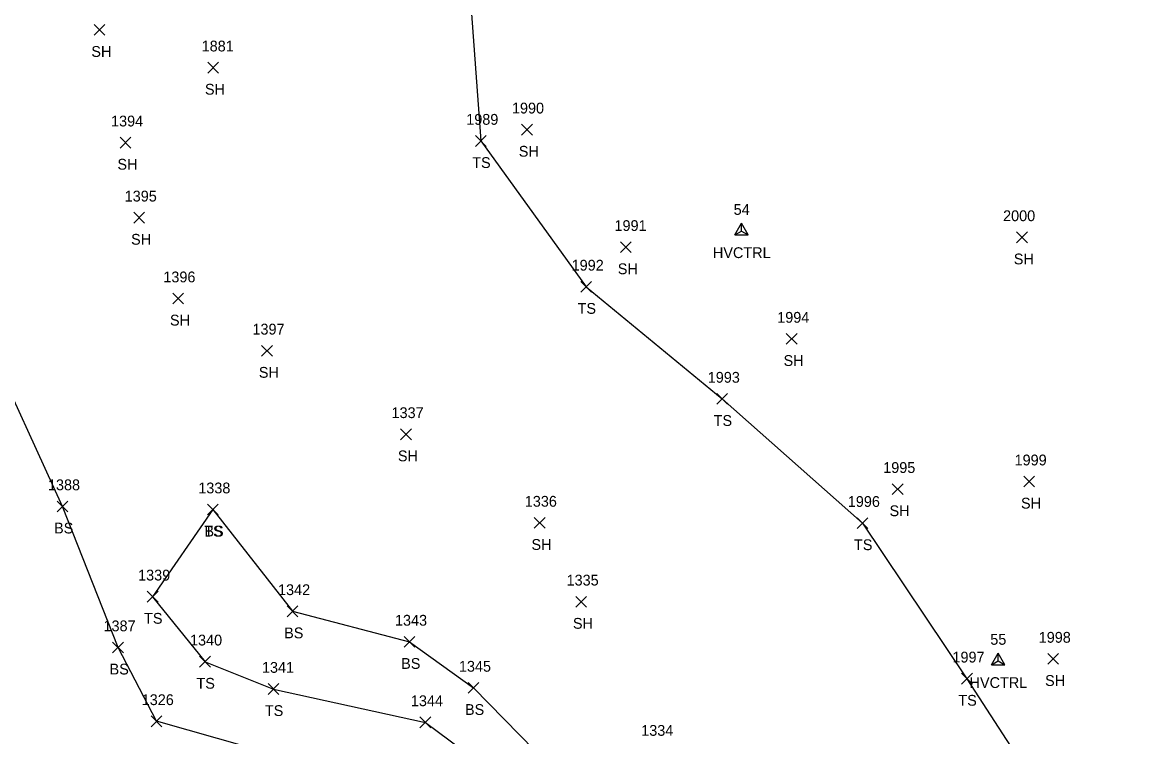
# Model space of a CAD drawing. Extents: x 1754529 to 1755810, y 621660 to 624656.
# Drawn here: x 1755214.3 to 1755421.2, y 623954.6 to 624086.9 of the extents above; entities that cross this region are included whole.
import ezdxf

# ---------------------------------------------------------------- set-up
doc = ezdxf.new("R2010")
doc.units = 0
for name, color, linetype in [('C_A', 7, 'Continuous'), ('C_I', 7, 'Continuous'), ('CPSM', 7, 'Continuous'), ('L_A', 7, 'Continuous'), ('L_I', 7, 'Continuous'), ('L_TIC', 7, 'Continuous'), ('LELB', 7, 'Continuous')]:
    doc.layers.add(name, color=color, linetype=linetype)

msp = doc.modelspace()

# ---------------------------------------------------------------- linework, layer by layer
at = {"layer": 'CPSM'}
for p, q in [((1755346.33, 624047.49), (1755347.58, 624049.66)), ((1755348.83, 624047.49), (1755347.58, 624049.66)), ((1755347.58, 624048.21), (1755347.58, 624049.66)), ((1755346.33, 624047.49), (1755347.58, 624048.21)), ((1755346.33, 624047.49), (1755348.83, 624047.49)), ((1755347.58, 624048.21), (1755347.58, 624048.21)), ((1755347.58, 624048.21), (1755348.83, 624047.49)), ((1755393.87, 623967.88), (1755395.12, 623970.04)), ((1755396.37, 623967.88), (1755395.12, 623970.04)), ((1755395.12, 623968.6), (1755395.12, 623970.04)), ((1755393.87, 623967.88), (1755395.12, 623968.6)), ((1755393.87, 623967.88), (1755396.37, 623967.88)), ((1755395.12, 623968.6), (1755395.12, 623968.6)), ((1755395.12, 623968.6), (1755396.37, 623967.88))]:
    msp.add_line(p, q, dxfattribs=at)
at = {"layer": 'L_TIC'}
for points in [[(1755227.62, 624084.47), (1755229.62, 624086.47)], [(1755229.62, 624084.47), (1755227.62, 624086.47)], [(1755248.66, 624077.48), (1755250.66, 624079.48)], [(1755250.66, 624077.48), (1755248.66, 624079.48)], [(1755306.81, 624065.99), (1755308.81, 624067.99)], [(1755308.81, 624065.99), (1755306.81, 624067.99)], [(1755232.44, 624063.59), (1755234.44, 624065.59)], [(1755234.44, 624063.59), (1755232.44, 624065.59)], [(1755298.26, 624063.9), (1755300.26, 624065.9)], [(1755300.26, 624063.9), (1755298.26, 624065.9)], [(1755234.97, 624049.69), (1755236.97, 624051.69)], [(1755236.97, 624049.69), (1755234.97, 624051.69)], [(1755398.53, 624046.05), (1755400.53, 624048.05)], [(1755400.53, 624046.05), (1755398.53, 624048.05)], [(1755325.15, 624044.23), (1755327.15, 624046.23)], [(1755327.15, 624044.23), (1755325.15, 624046.23)], [(1755317.78, 624036.89), (1755319.78, 624038.89)], [(1755319.78, 624036.89), (1755317.78, 624038.89)], [(1755242.19, 624034.72), (1755244.19, 624036.72)], [(1755244.19, 624034.72), (1755242.19, 624036.72)], [(1755355.87, 624027.24), (1755357.87, 624029.24)], [(1755357.87, 624027.24), (1755355.87, 624029.24)], [(1755258.65, 624025.05), (1755260.65, 624027.05)], [(1755260.65, 624025.05), (1755258.65, 624027.05)], [(1755343, 624016.13), (1755345, 624018.13)], [(1755345, 624016.13), (1755343, 624018.13)], [(1755284.41, 624009.58), (1755286.41, 624011.58)], [(1755286.41, 624009.58), (1755284.41, 624011.58)], [(1755375.51, 623999.42), (1755377.51, 624001.42)], [(1755377.51, 623999.42), (1755375.51, 624001.42)], [(1755399.86, 624000.82), (1755401.86, 624002.82)], [(1755401.86, 624000.82), (1755399.86, 624002.82)], [(1755220.75, 623996.22), (1755222.75, 623998.22)], [(1755222.75, 623996.22), (1755220.75, 623998.22)], [(1755248.6, 623995.64), (1755250.6, 623997.64)], [(1755250.6, 623995.64), (1755248.6, 623997.64)], [(1755248.6, 623995.64), (1755250.6, 623997.64)], [(1755250.6, 623995.64), (1755248.6, 623997.64)], [(1755309.16, 623993.17), (1755311.16, 623995.17)], [(1755311.16, 623993.17), (1755309.16, 623995.17)], [(1755369, 623993.13), (1755371, 623995.13)], [(1755371, 623993.13), (1755369, 623995.13)], [(1755237.46, 623979.5), (1755239.46, 623981.5)], [(1755239.46, 623979.5), (1755237.46, 623981.5)], [(1755316.84, 623978.57), (1755318.84, 623980.57)], [(1755318.84, 623978.57), (1755316.84, 623980.57)], [(1755263.38, 623976.8), (1755265.38, 623978.8)], [(1755265.38, 623976.8), (1755263.38, 623978.8)], [(1755231.04, 623970.1), (1755233.04, 623972.1)], [(1755233.04, 623970.1), (1755231.04, 623972.1)], [(1755285.06, 623971.14), (1755287.06, 623973.14)], [(1755287.06, 623971.14), (1755285.06, 623973.14)], [(1755404.32, 623967.98), (1755406.32, 623969.98)], [(1755406.32, 623967.98), (1755404.32, 623969.98)], [(1755247.16, 623967.47), (1755249.16, 623969.47)], [(1755249.16, 623967.47), (1755247.16, 623969.47)], [(1755388.34, 623964.32), (1755390.34, 623966.32)], [(1755390.34, 623964.32), (1755388.34, 623966.32)], [(1755259.84, 623962.41), (1755261.84, 623964.41)], [(1755261.84, 623962.41), (1755259.84, 623964.41)], [(1755296.89, 623962.61), (1755298.89, 623964.61)], [(1755298.89, 623962.61), (1755296.89, 623964.61)], [(1755238.18, 623956.43), (1755240.18, 623958.43)], [(1755240.18, 623956.43), (1755238.18, 623958.43)], [(1755287.99, 623956.23), (1755289.99, 623958.23)], [(1755289.99, 623956.23), (1755287.99, 623958.23)]]:
    msp.add_lwpolyline(points, dxfattribs=at)
at = {"layer": 'LELB'}
for points in [[(1755283.63, 624321.58), (1755261.89, 624310.21), (1755241.28, 624298.92), (1755225.63, 624290.24), (1755219.57, 624277.64), (1755236.29, 624268.09), (1755239.17, 624251.56), (1755235.61, 624235.54), (1755253.41, 624214.52), (1755275.93, 624188.95), (1755280.26, 624179.83), (1755294.83, 624178.69), (1755307.15, 624169.54), (1755309.03, 624155.09), (1755307.67, 624133.57), (1755296.24, 624106.15), (1755299.26, 624064.9), (1755318.78, 624037.89), (1755344, 624017.13), (1755370, 623994.13), (1755389.34, 623965.32), (1755402.54, 623944.92), (1755412.5, 623921.31), (1755426.67, 623899.96)], [(1755286.2, 623944.29), (1755267.63, 623949.34), (1755239.18, 623957.43), (1755232.04, 623971.1), (1755221.75, 623997.22), (1755207.57, 624028.22), (1755193.15, 624052.21), (1755209.59, 624065.41), (1755204.71, 624097.4), (1755197.92, 624122.33)], [(1755249.6, 623996.64), (1755238.46, 623980.5), (1755248.16, 623968.47), (1755260.84, 623963.41), (1755288.99, 623957.23), (1755313.55, 623939), (1755325.62, 623928.08)], [(1755249.6, 623996.64), (1755264.38, 623977.8), (1755286.06, 623972.14), (1755297.89, 623963.61), (1755317.78, 623943.33), (1755325.62, 623928.08)]]:
    msp.add_lwpolyline(points, dxfattribs=at)

# ---------------------------------------------------------------- texts
at = {"layer": 'C_A'}
for p in [(1755342.27, 624043.21), (1755389.82, 623963.6)]:
    msp.add_text('HVCTRL', height=2, dxfattribs=at).set_placement(p)
at = {"layer": 'C_I'}
for s, p in [('54', (1755346.11, 624051.21)), ('55', (1755393.66, 623971.6))]:
    msp.add_text(s, height=2, dxfattribs=at).set_placement(p)
at = {"layer": 'L_A'}
for s, p in [('SH', (1755227.1, 624080.47)), ('SH', (1755248.15, 624073.48)), ('SH', (1755306.3, 624061.99)), ('SH', (1755231.93, 624059.59)), ('TS', (1755297.67, 624059.9)), ('SH', (1755234.46, 624045.69)), ('SH', (1755324.64, 624040.23)), ('SH', (1755398.02, 624042.05)), ('TS', (1755317.19, 624032.89)), ('SH', (1755241.67, 624030.72)), ('SH', (1755355.36, 624023.24)), ('SH', (1755258.14, 624021.05)), ('TS', (1755342.41, 624012.13)), ('SH', (1755283.9, 624005.58)), ('SH', (1755399.35, 623996.82)), ('SH', (1755375, 623995.42)), ('BS', (1755220.19, 623992.22)), ('TS', (1755248.01, 623991.64)), ('BS', (1755248.05, 623991.64)), ('SH', (1755308.65, 623989.17)), ('TS', (1755368.41, 623989.13)), ('TS', (1755236.87, 623975.5)), ('SH', (1755316.33, 623974.57)), ('BS', (1755262.82, 623972.8)), ('BS', (1755230.48, 623966.1)), ('BS', (1755284.5, 623967.14)), ('SH', (1755403.81, 623963.98)), ('TS', (1755246.57, 623963.47)), ('TS', (1755387.75, 623960.32)), ('TS', (1755259.25, 623958.41)), ('BS', (1755296.33, 623958.61))]:
    msp.add_text(s, height=2, dxfattribs=at).set_placement(p)
at = {"layer": 'L_I'}
for s, p in [('1881', (1755247.54, 624081.48)), ('1990', (1755305.03, 624069.99)), ('1394', (1755230.75, 624067.59)), ('1989', (1755296.56, 624067.9)), ('1395', (1755233.28, 624053.69)), ('2000', (1755396.03, 624050.05)), ('1991', (1755324.03, 624048.23)), ('1992', (1755316.09, 624040.89)), ('1396', (1755240.44, 624038.72)), ('1994', (1755354.18, 624031.24)), ('1397', (1755256.95, 624029.05)), ('1993', (1755341.31, 624020.13)), ('1337', (1755282.72, 624013.58)), ('1995', (1755373.82, 624003.42)), ('1999', (1755398.16, 624004.82)), ('1388', (1755219.06, 624000.22)), ('1338', (1755246.91, 623999.64)), ('1338', (1755246.91, 623999.64)), ('1336', (1755307.41, 623997.17)), ('1996', (1755367.26, 623997.13)), ('1339', (1755235.76, 623983.5)), ('1335', (1755315.15, 623982.57)), ('1342', (1755261.69, 623980.8)), ('1387', (1755229.35, 623974.1)), ('1343', (1755283.36, 623975.14)), ('1998', (1755402.63, 623971.98)), ('1340', (1755245.38, 623971.47)), ('1997', (1755386.65, 623968.32)), ('1341', (1755258.71, 623966.41)), ('1345', (1755295.2, 623966.61)), ('1326', (1755236.43, 623960.43)), ('1344', (1755286.3, 623960.23)), ('1334', (1755328.98, 623954.74))]:
    msp.add_text(s, height=2, dxfattribs=at).set_placement(p)

doc.saveas('drawing.dxf')
